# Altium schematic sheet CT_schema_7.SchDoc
size 278 x 170 mm
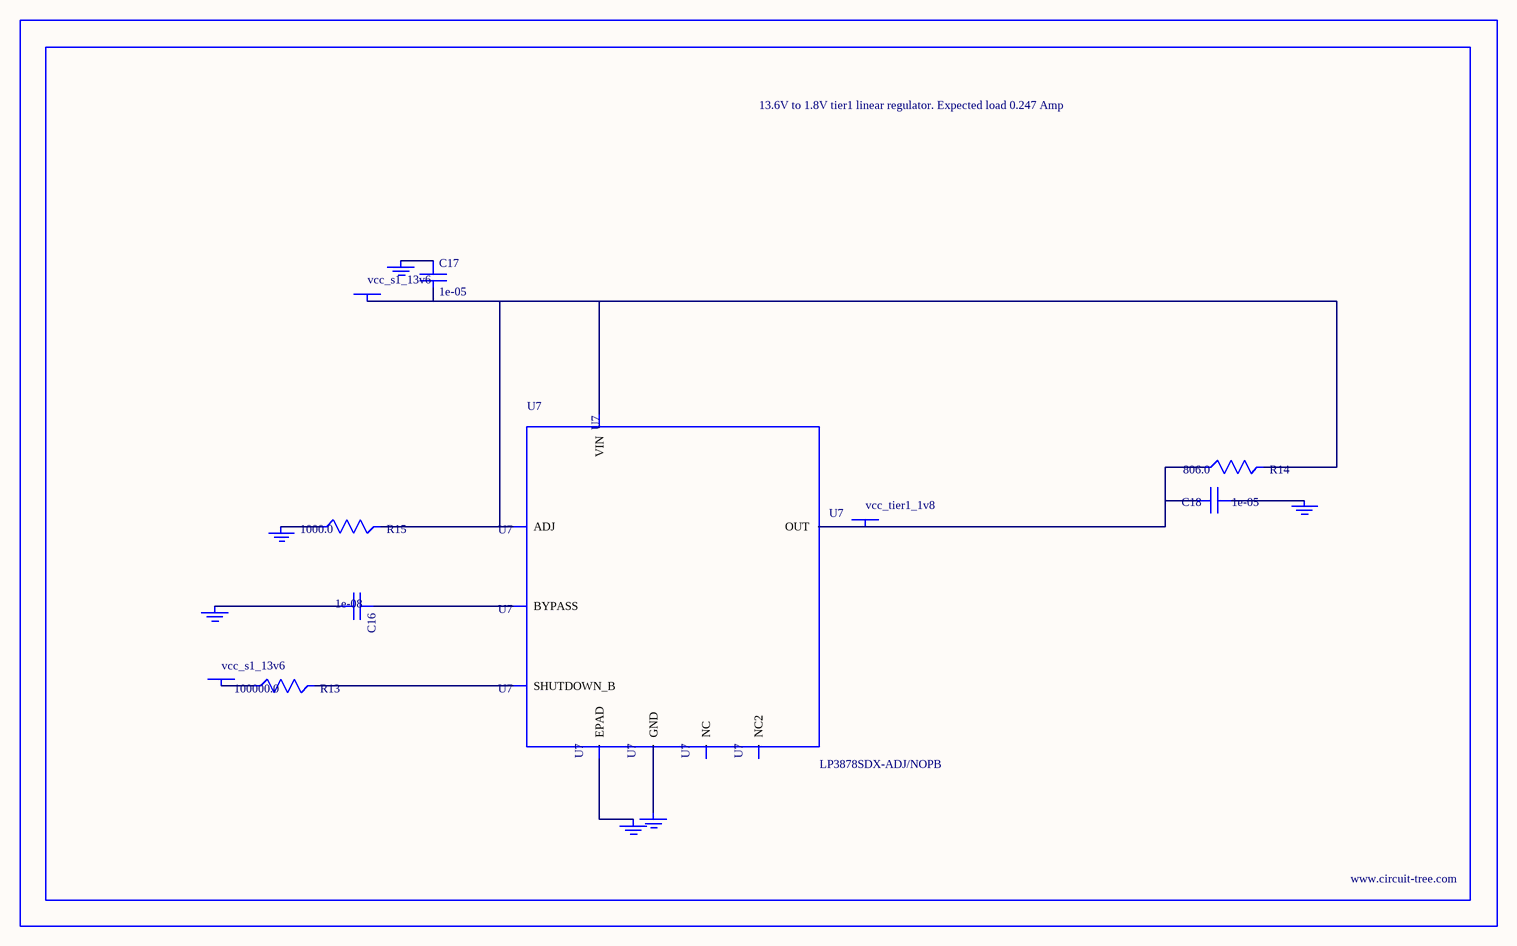
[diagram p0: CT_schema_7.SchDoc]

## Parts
BORDER6  (no value)
C16  1e-08  [C0402]
C17  1e-05  [C1210]
C18  1e-05  [C0805]
GND_INSTANCE_6_0  (no value)
GND_INSTANCE_6_1  (no value)
GND_INSTANCE_6_2  (no value)
GND_INSTANCE_6_3  (no value)
GND_INSTANCE_6_4  (no value)
GND_INSTANCE_6_5  (no value)
POWER_INSTANCE_6_0  vcc_s1_13v6
POWER_INSTANCE_6_1  vcc_s1_13v6
POWER_INSTANCE_6_2  vcc_tier1_1v8
R13  100000.0  [R0603]
R14  806.0  [R0603]
R15  1000.0  [R0603]
U7  LP3878SDX-ADJ/NOPB  [WSON-8]

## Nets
NetC16_1: C16.1 U7.1(BYPASS)
NetC16_2: C16.2 GND_INSTANCE_6_0.0(GND)
NetC17_1: C17.1 GND_INSTANCE_6_1.0(GND)
NetC17_2: C17.2 POWER_INSTANCE_6_0.0(PWR) R14.2 R15.2 U7.4(VIN) U7.6(ADJ)
NetC18_1: C18.1 GND_INSTANCE_6_2.0(GND)
NetC18_2: C18.2 POWER_INSTANCE_6_2.0(PWR) R14.1 U7.5(OUT)
NetGND_INSTANCE_6_3_0: GND_INSTANCE_6_3.0(GND) R15.1
NetGND_INSTANCE_6_4_0: GND_INSTANCE_6_4.0(GND) U7.PAD(EPAD)
NetGND_INSTANCE_6_5_0: GND_INSTANCE_6_5.0(GND) U7.3(GND)
NetPOWER_INSTANCE_6_1_0: POWER_INSTANCE_6_1.0(PWR) R13.1
NetR13_2: R13.2 U7.8(SHUTDOWN_B)

Not connected (* = marked no-connect by the designer): U7 2(NC) 7(NC2)

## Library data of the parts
BORDER6 = BORDER_PAGE6
C16 = C0402C103K3RAC
C17 = C1210C106K5PACTU
C18 = GRM219R60J106ME19D
GND_INSTANCE_6_0-GND_INSTANCE_6_5 = GND
POWER_INSTANCE_6_0-POWER_INSTANCE_6_2 = PWR
R13 = RC0603JR-07100KL
R14 = ERJ-3EKF8060V
R15 = RC0603JR-071KL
